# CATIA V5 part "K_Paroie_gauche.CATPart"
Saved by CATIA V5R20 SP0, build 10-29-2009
Part number: Coffre
Publications: "epaisseurplaques"
Bounding box of the stored display mesh (mm): x -5 to 330.41, y -415 to 5, z -265 to 0
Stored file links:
  G:\Khaled_CFAO_2011\SIL\SIL_GR2\zthiebault\Khaled\CAD_ThinkMOTION\K_Paroie_gauche.CATPart
  F:\Projet Thinkmotion\Catia\FINAL\HabillageFinal.CATProduct
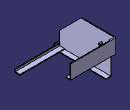
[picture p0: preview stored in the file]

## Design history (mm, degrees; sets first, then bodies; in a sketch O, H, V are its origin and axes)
Parameters
  epaisseurplaques = 5 mm
External parameters (linked from other documents)
  External.demilargeur_bras24 = 5 mm
  External.long_pivot_coffre = 14 mm
Set1
  Point1 "Point_base_coffre1": linked copy from another document
  Point2 "Point_base_coffre7": linked copy from another document
  Point3 "Point_base_coffre2": linked copy from another document
  Point4 "Point_base_coffre6": linked copy from another document
  Point5 "Point_base_coffre5": linked copy from another document
  Point6 "Point_base_coffre4": linked copy from another document
  Point7 "Point_base_coffre3": linked copy from another document
  Line1 "Droite_base__coffre2": linked copy from another document
  Plane1 "Plansymétrieensemble": linked copy from another document
  Line2 "Droite_base_coffre1": linked copy from another document
  Plane2: linked copy from another document
Set2
  Plane3: type OffsetPt, RefPlane xy-plane, RefPoint Point5
  Point8 "Point_base_coffre4": stored without definition
Body1 (main body)
  Sketch1 on yz-plane, origin (0, 0, 0), H (0, 1, 0), V (0, 0, 1)
    point P1 (-410, -260)
    line L1 (-410, -260) -> (-410, -160)
    point P2 (-410, -160)
    line L2 (-410, -160) -> (-250, 0)
    point P3 (-250, 0)
    line L3 (-250, 0) -> (0, 0)
    point P4 (0, 0)
    line L4 (0, 0) -> (0, -100)
    point P5 (0, -100)
    line L5 (0, -100) -> (-30, -100)
    point P6 (-30, -100)
    line L6 (-30, -100) -> (-30, -260)
    point P7 (-30, -260)
    line L7 (-30, -260) -> (-410, -260)
    reference projected point E1 (0, 0) from Point1
    reference projected point E2 (0, -100) from Point2
    reference projected point E3 (-250, 0) from Point3
    reference projected point E4 (-30, -100) from Point4
    reference projected point E5 (-30, -260) from Point5
    reference projected point E6 (-410, -260) from Point6
    reference projected point E7 (-410, -160) from Point7
    vertical: L1 V, L4 V, L6 V
    horizontal: L3 H, L5 H
    coincidence: E1 P4, P5 E2, P3 E3, P6 E4, P7 E5, P1 E6, P2 E7
  Pad1: profile Sketch1, direction (-1, 0, 0), length 5 {= epaisseurplaques}
  Sketch2 on Plane3, origin (0, 0, -260), H (1, 0, 0), V (0, 1, 0)
    point P1 (-5, -30)
    line L1 (-5, -30) -> (35, -30)
    line L2 (35, -30) -> (35, -410)
    line L3 (35, -410) -> (-5, -410)
    line L4 (-5, -410) -> (-5, -30)
    point P4 (-5, -410)
    reference projected line E1 (0, -410) -> (0, -30) from Line1
    reference projected point E2 (0, -410) from Point8
    reference projected point E3 (0, -410) from Point8
    reference projected point E4 (0, -410) from Point8
    reference projected point E5 (0, -30) from Point5
    reference projected point E6 (0, -30) from Point5
    length L3 = 40
    distance E2 E3 = 0 (reference)
    distance P4 E4 = 5 {= epaisseurplaques}
    distance E5 P1 = 5 {= epaisseurplaques}
    horizontal: L1 H, L3 H
    vertical: L2 V, L4 V
    parallelism: L4 E1
    coincidence: L1 E6
  Pad2: profile Sketch2, direction (0, 0, 1), length 0, opposite side length 5 {= epaisseurplaques}
  Sketch3 on face of Pad2, origin (0, -410, 0), H (1, 0, 0), V (0, 0, 1)
    line L1 (-5, -230) -> (35, -230)
    line L2 (35, -230) -> (35, -265)
    line L3 (35, -265) -> (-5, -265)
    line L4 (-5, -265) -> (-5, -230)
    reference projected line E1 (-5, -265) -> (35, -265) from edge [start face of Pad2 | face of Pad2]
    reference projected line E2 (-5, -260) -> (-5, -160) from edge [face of Pad2 | face of Pad2]
    reference projected line E3 (35, -262.5) -> (35, -257.5) from edge [face of Pad2 from Sketch2.L2 | face of Pad2 from Sketch2.L3]
    length L2 = 35
    horizontal: L1 H, L3 H
    vertical: L2 V, L4 V
    coincidence: E1 L3, E2 L4, L2 E3
  Pad3: profile Sketch3, direction (0, -1, 0), length 5 {= epaisseurplaques}
  Sketch4 on face of Pad1 from Sketch1.L4, origin (0, 0, 0), H (-1, 0, 0), V (0, 0, 1)
    line L1 (-35, 0) -> (5, 0)
    line L2 (5, 0) -> (5, -100)
    line L3 (5, -100) -> (-35, -100)
    line L4 (-35, -100) -> (-35, 0)
    reference projected line E1 (5, -100) -> (5, 0) from edge [end face of Pad1 | face of Pad1 from Sketch1.L4]
    reference projected line E2 (-35, -257.5) -> (-35, -227.5) from edge [start face of Pad3 | face of Pad3]
    reference intersected line E3 (0, 0) -> (5, 0) from face of Pad1 from Sketch1.L3
    reference intersected line E4 (5, -100) -> (0, -100) from face of Pad1 from Sketch1.L5
    horizontal: L1 H, L3 H
    vertical: L2 V, L4 V
    coincidence: E1 L2, L4 E2, L1 E3, E4 L3
  Pad4: profile Sketch4, direction (0, -1, 0), length 5 {= epaisseurplaques}
  Sketch5 on face of Pad4 from Sketch4.L4, origin (35, 0, 0), H (0, 1, 0), V (0, 0, 1)
    line L1 (-30, -100) -> (0, -100)
    line L2 (0, -100) -> (0, 0)
    line L3 (0, 0) -> (5, 0)
    line L4 (5, 0) -> (5, -105)
    line L5 (5, -105) -> (-30, -105)
    line L6 (-30, -105) -> (-30, -100)
    reference intersected line E1 through (0, 0) direction (0, 1) from face of Pad4
    reference intersected line E2 through (0, -100) direction (1, 0) from face of Pad4
    reference intersected line E3 through (-30, 0) direction (0, 1) from face of Pad2
    reference intersected line E4 through (0, 0) direction (-1, 0) from face of Pad4
    length L3 = 5 {= epaisseurplaques}
    length L6 = 5 {= epaisseurplaques}
    horizontal: L1 H, L3 H, L5 H
    vertical: L2 V, L4 V, L6 V
    coincidence: L2 E1, E2 L1, E3 L6, E4 L3
  Pad5: profile Sketch5, direction (1, 0, 0), up to Plane1, opposite side up to yz-plane, offset 5 {= epaisseurplaques}
  Sketch6 on start face of Pad1, origin (0, 0, 0), H (0, 1, 0), V (0, 0, 1)
    line L1 (-405, -240) -> (-405, -255)
    line L2 (-405, -255) -> (-370, -255)
    line L3 (-370, -255) -> (-370, -260)
    line L4 (-370, -260) -> (-410, -260)
    line L5 (-410, -260) -> (-410, -240)
    line L6 (-410, -240) -> (-405, -240)
    reference intersected line E1 (-410, -227.5) -> (-410, -262.5) from start face of Pad3
    reference intersected line E2 (-410, -260) -> (-30, -260) from end face of Pad2
    length L3 = 5 {= epaisseurplaques}
    length L6 = 5 {= epaisseurplaques}
    length L4 = 40
    length L5 = 20
    vertical: L1 V, L3 V, L5 V
    horizontal: L2 H, L4 H, L6 H
    coincidence: L5 E1, E2 L4
  Pad6: profile Sketch6, direction (1, 0, 0), up to Plane1
  Sketch7 on start face of Pad1, origin (0, 0, 0), H (0, 1, 0), V (0, 0, 1)
    circle A1 centre (-96.5, -82) radius 8
    point P1 (-96.5, -82)
    reference projected point E1 (-96.5, -82) from Line2
    radius A1 = 8 {= External.demilargeur_bras24 +3mm}
    coincidence: P1 E1
  Pad7: profile Sketch7, direction (1, 0, 0), up to Plane2, offset -2.5
  Sketch8 on end face of Pad7, origin (17.91, -96.5, -82), H (0, 1, 0), V (0, 0, 1)
    point P1 (0, 0)
    reference projected point E1 (0, 0) from Line2
    coincidence: P1 E1
  Hole1: placed by Sketch8, at (17.91, -96.5, -82) direction (-1, 0, 0), diameter 10 {= External.demilargeur_bras24 *2}, depth 14 {= External.long_pivot_coffre}
  Fillet1: radius 2, on edge [face of Pad4 | end face of Pad3]; edge [face of Pad3 | end face of Pad3]; edge [face of Pad3 | face of Pad4]; edge [face of Pad3 | face of Pad2]; edge [face of Pad4 | face of Pad2]; edge [face of Pad4 | face of Pad5 from Sketch5.L4]; edge [face of Pad4 | face of Pad5 from Sketch5.L5]; edge [face of Pad5 from Sketch5.L5 | face of Pad5 from Sketch5.L4]; edge [face of Pad6 from Sketch6.L4 | face of Pad6 from Sketch6.L5]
